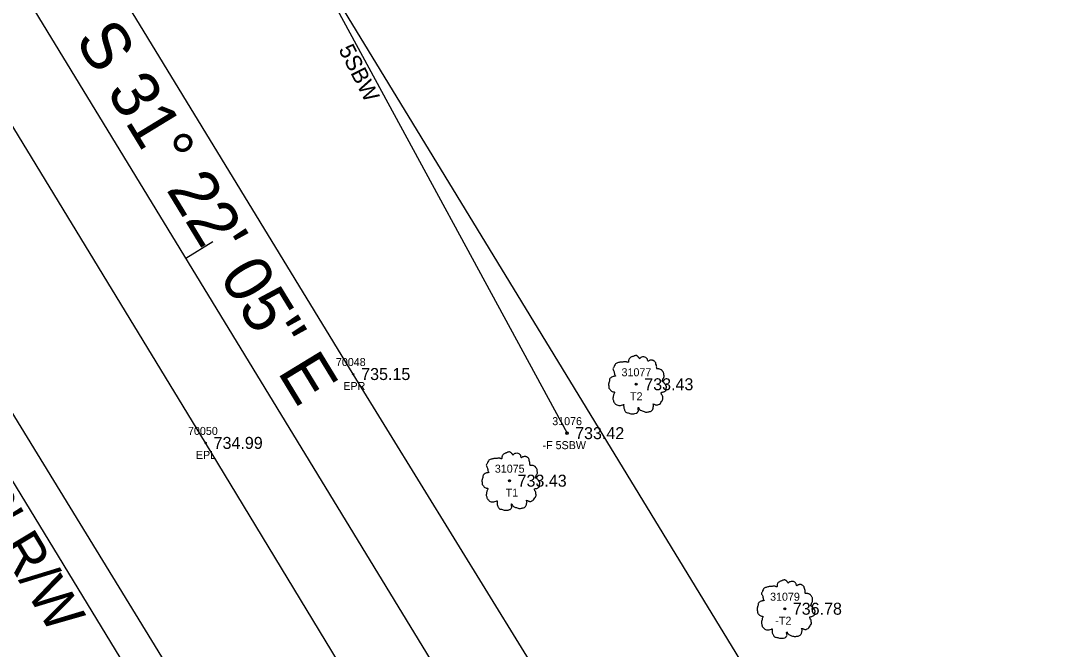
# Model space of a CAD drawing. Extents: x 1375131 to 1378678, y 999028 to 1004053.
# Drawn here: x 1377739.9 to 1377868.1, y 1000960.8 to 1001039.4 of the extents above; entities that cross this region are included whole.
import ezdxf

# ---------------------------------------------------------------- set-up
doc = ezdxf.new("R2010")
doc.units = 0
for name, color, linetype in [('RD_EX_Fence_Other', 7, 'Continuous'), ('RD_EX_Fence_Other_txCode', 7, 'Continuous'), ('RD_EX_Road', 7, 'Continuous'), ('RD_EX_Road_txCode', 7, 'Continuous'), ('RD_EX_RW', 7, 'Continuous'), ('RD_EX_RW_TX', 7, 'Continuous'), ('RD_EX_SU_Elec', 7, 'Continuous'), ('RD_EX_TX_Fence_Other_ELEV', 7, 'Continuous'), ('RD_EX_TX_Road_ELEV', 7, 'Continuous'), ('RD_EX_TX_VEG_ELEV', 7, 'Continuous'), ('RD_EX_VEG', 7, 'Continuous'), ('RD_EX_VEG_txCode', 7, 'Continuous'), ('RD_HC_Cl', 7, 'Continuous'), ('RD_HC_Data', 7, 'Continuous'), ('RD_HC_Data_Tic', 7, 'Continuous'), ('RD_SMD_Locator', 7, 'Continuous'), ('RD_TX_Misc2', 7, 'Continuous')]:
    doc.layers.add(name, color=color, linetype=linetype)

msp = doc.modelspace()

# ---------------------------------------------------------------- linework, layer by layer
at = {"layer": 'RD_EX_Fence_Other'}
msp.add_line((1377746.17, 1001102.37), (1377808.24, 1000987.87), dxfattribs=at)
at = {"layer": 'RD_EX_Road'}
for points in [[(1377899.67, 1000800.29), (1377898.72, 1000801.84), (1377870.31, 1000849.94), (1377847.28, 1000887.89), (1377815.15, 1000940.58), (1377781.51, 1000995.26), (1377748.62, 1001049.21), (1377716.58, 1001099.53), (1377686.67, 1001148.78), (1377656.47, 1001199.11), (1377629.54, 1001244.18), (1377599.89, 1001292.67), (1377570.87, 1001341.43), (1377539.83, 1001392.47), (1377511.01, 1001440.31), (1377480.72, 1001490), (1377449.73, 1001541.49), (1377420.9, 1001591.95), (1377390.45, 1001644.41)], [(1377883.75, 1000788.5), (1377882.63, 1000790.22), (1377852.26, 1000839.6), (1377828.46, 1000879.31), (1377797, 1000930.66), (1377763.07, 1000986.65), (1377731.87, 1001037.81), (1377700.31, 1001089.98), (1377670.43, 1001138.24), (1377639.73, 1001190.03), (1377611.89, 1001234.23), (1377582.78, 1001282.57), (1377552.22, 1001331.03), (1377522.24, 1001382.35), (1377494.26, 1001430.19), (1377463.17, 1001481.14), (1377433.42, 1001531.29), (1377403.14, 1001580.98), (1377371.36, 1001632.19)]]:
    msp.add_lwpolyline(points, dxfattribs=at)
at = {"layer": 'RD_EX_RW'}
for p, q in [((1377592.75, 1001348.44), (1377983.57, 1000707.36)), ((1377536.4, 1001314.08), (1377927.22, 1000673.01))]:
    msp.add_line(p, q, dxfattribs=at)
at = {"layer": 'RD_EX_SU_Elec'}
msp.add_lwpolyline([(1377525.76, 1001454.69), (1377578.78, 1001251.81), (1377798.03, 1000893.79)], dxfattribs=at)
at = {"layer": 'RD_EX_VEG'}
for centre, radius in [((1377816.88, 1000993.98), 0.125), ((1377816.87, 1000993.97), 0.00005), ((1377801.05, 1000981.93), 0.125), ((1377801.04, 1000981.92), 0.00005), ((1377835.44, 1000965.93), 0.125), ((1377835.43, 1000965.92), 0.00005)]:
    msp.add_circle(centre, radius, dxfattribs=at)
for points in [[(1377816.94, 1000997.56), (1377816.79, 1000997.57), (1377816.63, 1000997.52), (1377816.5, 1000997.47), (1377816.39, 1000997.44), (1377816.28, 1000997.39), (1377816.13, 1000997.3), (1377816.02, 1000997.2), (1377815.95, 1000997.07), (1377815.93, 1000996.96), (1377815.9, 1000996.82), (1377815.9, 1000996.74), (1377815.84, 1000996.72), (1377815.77, 1000996.74), (1377815.64, 1000996.77), (1377815.52, 1000996.77), (1377815.39, 1000996.77), (1377815.22, 1000996.76), (1377815.04, 1000996.76), (1377814.9, 1000996.74), (1377814.74, 1000996.71), (1377814.55, 1000996.65), (1377814.38, 1000996.59), (1377814.23, 1000996.46), (1377814.1, 1000996.22), (1377814.04, 1000996.05), (1377813.97, 1000995.92), (1377814.04, 1000995.7), (1377814.13, 1000995.53), (1377814.14, 1000995.43), (1377814.18, 1000995.21), (1377814.23, 1000995.1), (1377814.29, 1000995), (1377814.25, 1000994.99), (1377814.07, 1000994.96), (1377813.92, 1000994.91), (1377813.7, 1000994.8), (1377813.59, 1000994.69), (1377813.54, 1000994.53), (1377813.53, 1000994.35), (1377813.48, 1000994.25), (1377813.44, 1000994.11), (1377813.43, 1000994.08), (1377813.41, 1000993.91), (1377813.46, 1000993.69), (1377813.47, 1000993.51), (1377813.53, 1000993.4), (1377813.6, 1000993.31), (1377813.69, 1000993.19), (1377813.89, 1000993.08), (1377814.05, 1000993.03), (1377814.15, 1000993.01), (1377814.07, 1000992.76), (1377814.04, 1000992.59), (1377813.98, 1000992.39), (1377813.98, 1000992.35), (1377813.95, 1000992.11), (1377814.03, 1000991.95), (1377814.07, 1000991.76), (1377814.15, 1000991.65), (1377814.29, 1000991.5), (1377814.45, 1000991.39), (1377814.7, 1000991.33), (1377814.9, 1000991.34), (1377815.19, 1000991.43), (1377815.32, 1000991.46), (1377815.3, 1000991.38), (1377815.32, 1000991.19), (1377815.32, 1000990.98), (1377815.39, 1000990.81), (1377815.44, 1000990.68), (1377815.52, 1000990.55), (1377815.68, 1000990.44), (1377815.88, 1000990.4), (1377816.09, 1000990.33), (1377816.32, 1000990.29), (1377816.57, 1000990.28), (1377816.87, 1000990.35), (1377817, 1000990.41), (1377817.05, 1000990.5), (1377817.15, 1000990.69), (1377817.13, 1000990.8), (1377817.14, 1000991.1), (1377817.19, 1000991.01), (1377817.28, 1000990.84), (1377817.53, 1000990.69), (1377817.73, 1000990.6), (1377817.97, 1000990.53), (1377818.12, 1000990.49), (1377818.35, 1000990.53), (1377818.54, 1000990.56), (1377818.73, 1000990.63), (1377818.88, 1000990.76), (1377818.97, 1000990.9), (1377818.99, 1000991.04), (1377819.03, 1000991.23), (1377819.05, 1000991.31)], [(1377819.05, 1000991.31), (1377819.02, 1000991.4), (1377818.99, 1000991.53), (1377819.03, 1000991.51), (1377819.12, 1000991.49), (1377819.25, 1000991.43), (1377819.36, 1000991.39), (1377819.53, 1000991.4), (1377819.66, 1000991.45), (1377819.89, 1000991.59), (1377820.03, 1000991.83), (1377820.16, 1000992.03), (1377820.2, 1000992.19), (1377820.18, 1000992.3), (1377820.16, 1000992.55), (1377820.06, 1000992.68), (1377820.04, 1000992.74), (1377819.99, 1000992.94), (1377820.03, 1000992.96), (1377820.16, 1000992.99), (1377820.35, 1000993.05), (1377820.49, 1000993.11), (1377820.6, 1000993.2), (1377820.64, 1000993.31), (1377820.63, 1000993.51), (1377820.65, 1000993.71), (1377820.61, 1000993.79), (1377820.56, 1000993.86), (1377820.53, 1000993.96), (1377820.45, 1000994.04), (1377820.4, 1000994.11), (1377820.35, 1000994.16), (1377820.29, 1000994.24), (1377820.2, 1000994.3), (1377820.13, 1000994.33), (1377820.1, 1000994.4), (1377820.18, 1000994.5), (1377820.2, 1000994.55), (1377820.21, 1000994.66), (1377820.33, 1000994.84), (1377820.35, 1000995.04), (1377820.33, 1000995.25), (1377820.3, 1000995.39), (1377820.23, 1000995.53), (1377820.13, 1000995.65), (1377820.06, 1000995.74), (1377819.98, 1000995.8), (1377819.81, 1000995.86), (1377819.69, 1000995.89), (1377819.51, 1000995.89), (1377819.41, 1000995.91), (1377819.43, 1000995.94), (1377819.43, 1000996.01), (1377819.43, 1000996.15), (1377819.39, 1000996.37), (1377819.31, 1000996.62), (1377819.31, 1000996.64), (1377819.26, 1000996.76), (1377819.15, 1000996.86), (1377819.07, 1000996.91), (1377818.97, 1000996.97), (1377818.84, 1000996.99), (1377818.69, 1000996.99), (1377818.55, 1000996.96), (1377818.45, 1000996.91), (1377818.37, 1000996.85), (1377818.33, 1000996.92), (1377818.28, 1000997.07), (1377818.25, 1000997.15), (1377818.18, 1000997.24), (1377818.07, 1000997.34), (1377817.84, 1000997.4), (1377817.53, 1000997.36), (1377817.38, 1000997.26), (1377817.3, 1000997.17), (1377817.28, 1000997.24), (1377817.18, 1000997.34), (1377817.13, 1000997.42), (1377817.04, 1000997.49), (1377816.97, 1000997.54), (1377816.92, 1000997.56)], [(1377801.11, 1000985.51), (1377800.97, 1000985.53), (1377800.8, 1000985.48), (1377800.68, 1000985.43), (1377800.57, 1000985.39), (1377800.45, 1000985.34), (1377800.3, 1000985.25), (1377800.19, 1000985.15), (1377800.13, 1000985.03), (1377800.1, 1000984.91), (1377800.08, 1000984.78), (1377800.08, 1000984.69), (1377800.02, 1000984.68), (1377799.94, 1000984.69), (1377799.82, 1000984.73), (1377799.69, 1000984.73), (1377799.57, 1000984.73), (1377799.39, 1000984.71), (1377799.22, 1000984.71), (1377799.08, 1000984.69), (1377798.92, 1000984.67), (1377798.73, 1000984.6), (1377798.55, 1000984.54), (1377798.4, 1000984.42), (1377798.28, 1000984.18), (1377798.22, 1000984), (1377798.14, 1000983.88), (1377798.22, 1000983.65), (1377798.3, 1000983.48), (1377798.32, 1000983.38), (1377798.35, 1000983.17), (1377798.4, 1000983.05), (1377798.47, 1000982.95), (1377798.43, 1000982.94), (1377798.24, 1000982.92), (1377798.09, 1000982.87), (1377797.88, 1000982.75), (1377797.77, 1000982.64), (1377797.72, 1000982.48), (1377797.7, 1000982.3), (1377797.65, 1000982.2), (1377797.62, 1000982.07), (1377797.6, 1000982.03), (1377797.58, 1000981.87), (1377797.63, 1000981.64), (1377797.64, 1000981.47), (1377797.7, 1000981.35), (1377797.78, 1000981.27), (1377797.87, 1000981.14), (1377798.07, 1000981.03), (1377798.23, 1000980.98), (1377798.33, 1000980.97), (1377798.24, 1000980.72), (1377798.22, 1000980.54), (1377798.15, 1000980.34), (1377798.15, 1000980.3), (1377798.13, 1000980.07), (1377798.2, 1000979.9), (1377798.24, 1000979.72), (1377798.33, 1000979.6), (1377798.47, 1000979.45), (1377798.63, 1000979.34), (1377798.88, 1000979.28), (1377799.08, 1000979.29), (1377799.37, 1000979.38), (1377799.49, 1000979.42), (1377799.48, 1000979.33), (1377799.49, 1000979.14), (1377799.49, 1000978.93), (1377799.57, 1000978.77), (1377799.62, 1000978.63), (1377799.69, 1000978.51), (1377799.85, 1000978.39), (1377800.05, 1000978.36), (1377800.27, 1000978.28), (1377800.49, 1000978.24), (1377800.74, 1000978.23), (1377801.04, 1000978.31), (1377801.18, 1000978.37), (1377801.23, 1000978.46), (1377801.33, 1000978.64), (1377801.3, 1000978.76), (1377801.31, 1000979.05), (1377801.36, 1000978.97), (1377801.45, 1000978.79), (1377801.7, 1000978.64), (1377801.9, 1000978.56), (1377802.14, 1000978.48), (1377802.29, 1000978.44), (1377802.53, 1000978.48), (1377802.71, 1000978.52), (1377802.9, 1000978.58), (1377803.05, 1000978.72), (1377803.14, 1000978.86), (1377803.16, 1000978.99), (1377803.2, 1000979.18), (1377803.23, 1000979.27)], [(1377803.23, 1000979.27), (1377803.19, 1000979.35), (1377803.16, 1000979.48), (1377803.2, 1000979.47), (1377803.29, 1000979.44), (1377803.43, 1000979.38), (1377803.54, 1000979.34), (1377803.7, 1000979.35), (1377803.84, 1000979.4), (1377804.06, 1000979.54), (1377804.2, 1000979.78), (1377804.34, 1000979.98), (1377804.38, 1000980.14), (1377804.35, 1000980.25), (1377804.34, 1000980.5), (1377804.24, 1000980.63), (1377804.21, 1000980.69), (1377804.16, 1000980.89), (1377804.2, 1000980.92), (1377804.34, 1000980.94), (1377804.53, 1000981), (1377804.66, 1000981.07), (1377804.78, 1000981.15), (1377804.81, 1000981.27), (1377804.8, 1000981.47), (1377804.83, 1000981.67), (1377804.79, 1000981.74), (1377804.74, 1000981.82), (1377804.7, 1000981.92), (1377804.63, 1000981.99), (1377804.58, 1000982.07), (1377804.53, 1000982.12), (1377804.46, 1000982.19), (1377804.38, 1000982.25), (1377804.3, 1000982.28), (1377804.28, 1000982.35), (1377804.35, 1000982.45), (1377804.38, 1000982.5), (1377804.39, 1000982.62), (1377804.5, 1000982.79), (1377804.53, 1000982.99), (1377804.5, 1000983.2), (1377804.48, 1000983.34), (1377804.4, 1000983.48), (1377804.3, 1000983.6), (1377804.24, 1000983.69), (1377804.15, 1000983.75), (1377803.99, 1000983.82), (1377803.86, 1000983.84), (1377803.69, 1000983.84), (1377803.59, 1000983.87), (1377803.6, 1000983.89), (1377803.6, 1000983.97), (1377803.6, 1000984.1), (1377803.56, 1000984.33), (1377803.49, 1000984.58), (1377803.49, 1000984.59), (1377803.44, 1000984.71), (1377803.33, 1000984.81), (1377803.24, 1000984.86), (1377803.14, 1000984.93), (1377803.01, 1000984.94), (1377802.86, 1000984.94), (1377802.73, 1000984.91), (1377802.63, 1000984.86), (1377802.54, 1000984.8), (1377802.5, 1000984.88), (1377802.45, 1000985.03), (1377802.43, 1000985.1), (1377802.35, 1000985.19), (1377802.24, 1000985.29), (1377802.01, 1000985.35), (1377801.7, 1000985.31), (1377801.55, 1000985.21), (1377801.48, 1000985.13), (1377801.45, 1000985.19), (1377801.35, 1000985.29), (1377801.3, 1000985.38), (1377801.21, 1000985.44), (1377801.14, 1000985.49), (1377801.09, 1000985.51)], [(1377835.5, 1000969.51), (1377835.36, 1000969.53), (1377835.19, 1000969.48), (1377835.07, 1000969.43), (1377834.96, 1000969.39), (1377834.84, 1000969.34), (1377834.69, 1000969.25), (1377834.58, 1000969.15), (1377834.52, 1000969.03), (1377834.49, 1000968.91), (1377834.47, 1000968.78), (1377834.47, 1000968.69), (1377834.41, 1000968.68), (1377834.33, 1000968.69), (1377834.21, 1000968.73), (1377834.08, 1000968.73), (1377833.96, 1000968.73), (1377833.78, 1000968.71), (1377833.61, 1000968.71), (1377833.47, 1000968.69), (1377833.31, 1000968.66), (1377833.12, 1000968.6), (1377832.94, 1000968.54), (1377832.79, 1000968.41), (1377832.67, 1000968.18), (1377832.61, 1000968), (1377832.53, 1000967.88), (1377832.61, 1000967.65), (1377832.69, 1000967.48), (1377832.71, 1000967.38), (1377832.74, 1000967.16), (1377832.79, 1000967.05), (1377832.86, 1000966.95), (1377832.82, 1000966.94), (1377832.63, 1000966.91), (1377832.48, 1000966.86), (1377832.27, 1000966.75), (1377832.16, 1000966.64), (1377832.11, 1000966.48), (1377832.09, 1000966.3), (1377832.04, 1000966.2), (1377832.01, 1000966.07), (1377831.99, 1000966.03), (1377831.97, 1000965.87), (1377832.02, 1000965.64), (1377832.03, 1000965.47), (1377832.09, 1000965.35), (1377832.17, 1000965.27), (1377832.26, 1000965.14), (1377832.46, 1000965.03), (1377832.62, 1000964.98), (1377832.72, 1000964.97), (1377832.63, 1000964.72), (1377832.61, 1000964.54), (1377832.54, 1000964.34), (1377832.54, 1000964.3), (1377832.52, 1000964.07), (1377832.59, 1000963.9), (1377832.63, 1000963.72), (1377832.72, 1000963.6), (1377832.86, 1000963.45), (1377833.02, 1000963.34), (1377833.27, 1000963.28), (1377833.47, 1000963.29), (1377833.76, 1000963.38), (1377833.88, 1000963.42), (1377833.87, 1000963.33), (1377833.88, 1000963.14), (1377833.88, 1000962.93), (1377833.96, 1000962.77), (1377834.01, 1000962.63), (1377834.08, 1000962.5), (1377834.24, 1000962.39), (1377834.44, 1000962.35), (1377834.66, 1000962.28), (1377834.88, 1000962.24), (1377835.13, 1000962.23), (1377835.43, 1000962.3), (1377835.57, 1000962.37), (1377835.62, 1000962.45), (1377835.72, 1000962.64), (1377835.69, 1000962.75), (1377835.7, 1000963.05), (1377835.75, 1000962.97), (1377835.84, 1000962.79), (1377836.09, 1000962.64), (1377836.29, 1000962.55), (1377836.53, 1000962.48), (1377836.68, 1000962.44), (1377836.92, 1000962.48), (1377837.1, 1000962.52), (1377837.29, 1000962.58), (1377837.44, 1000962.72), (1377837.53, 1000962.85), (1377837.55, 1000962.99), (1377837.59, 1000963.18), (1377837.62, 1000963.27)], [(1377837.62, 1000963.27), (1377837.58, 1000963.35), (1377837.55, 1000963.48), (1377837.59, 1000963.47), (1377837.68, 1000963.44), (1377837.82, 1000963.38), (1377837.93, 1000963.34), (1377838.09, 1000963.35), (1377838.23, 1000963.4), (1377838.45, 1000963.54), (1377838.59, 1000963.78), (1377838.73, 1000963.98), (1377838.77, 1000964.14), (1377838.74, 1000964.25), (1377838.73, 1000964.5), (1377838.63, 1000964.63), (1377838.6, 1000964.69), (1377838.55, 1000964.89), (1377838.59, 1000964.92), (1377838.73, 1000964.94), (1377838.92, 1000965), (1377839.05, 1000965.07), (1377839.17, 1000965.15), (1377839.2, 1000965.27), (1377839.19, 1000965.47), (1377839.22, 1000965.67), (1377839.18, 1000965.74), (1377839.13, 1000965.82), (1377839.09, 1000965.92), (1377839.02, 1000965.99), (1377838.97, 1000966.07), (1377838.92, 1000966.12), (1377838.85, 1000966.19), (1377838.77, 1000966.25), (1377838.69, 1000966.28), (1377838.67, 1000966.35), (1377838.74, 1000966.45), (1377838.77, 1000966.5), (1377838.78, 1000966.61), (1377838.89, 1000966.79), (1377838.92, 1000966.99), (1377838.89, 1000967.2), (1377838.87, 1000967.34), (1377838.79, 1000967.48), (1377838.69, 1000967.6), (1377838.63, 1000967.69), (1377838.54, 1000967.75), (1377838.38, 1000967.81), (1377838.25, 1000967.84), (1377838.08, 1000967.84), (1377837.98, 1000967.86), (1377837.99, 1000967.89), (1377837.99, 1000967.96), (1377837.99, 1000968.1), (1377837.95, 1000968.33), (1377837.88, 1000968.58), (1377837.88, 1000968.59), (1377837.83, 1000968.71), (1377837.72, 1000968.81), (1377837.63, 1000968.86), (1377837.53, 1000968.93), (1377837.4, 1000968.94), (1377837.25, 1000968.94), (1377837.12, 1000968.91), (1377837.02, 1000968.86), (1377836.93, 1000968.8), (1377836.89, 1000968.88), (1377836.84, 1000969.03), (1377836.82, 1000969.1), (1377836.74, 1000969.19), (1377836.63, 1000969.29), (1377836.4, 1000969.35), (1377836.09, 1000969.31), (1377835.94, 1000969.21), (1377835.87, 1000969.13), (1377835.84, 1000969.19), (1377835.74, 1000969.29), (1377835.69, 1000969.38), (1377835.6, 1000969.44), (1377835.53, 1000969.49), (1377835.48, 1000969.51)]]:
    msp.add_spline(points, degree=3, dxfattribs=at)
at = {"layer": 'RD_HC_Cl'}
msp.add_line((1377564.57, 1001331.26), (1377955.4, 1000690.18), dxfattribs=at)
at = {"layer": 'RD_HC_Data_Tic'}
msp.add_line((1377760.58, 1001009.75), (1377763.99, 1001011.83), dxfattribs=at)
at = {"layer": 'RD_SMD_Locator'}
for centre, radius in [((1377781.51, 1000995.26), 0.075), ((1377816.88, 1000993.98), 0.075), ((1377808.24, 1000987.87), 0.15), ((1377763.07, 1000986.65), 0.075), ((1377801.05, 1000981.93), 0.075), ((1377835.44, 1000965.93), 0.075)]:
    msp.add_circle(centre, radius, dxfattribs=at)

# ---------------------------------------------------------------- texts
at = {"layer": 'RD_EX_Fence_Other_txCode'}
for s, p in [('31076', (1377806.38, 1000988.87)), ('-F 5SBW', (1377805.17, 1000985.87))]:
    msp.add_text(s, height=1, dxfattribs=at).set_placement(p)
at = {"layer": 'RD_EX_Road_txCode'}
for s, p in [('70048', (1377779.35, 1000996.26)), ('EPR', (1377780.28, 1000993.26)), ('70050', (1377760.87, 1000987.65)), ('EPL', (1377761.86, 1000984.65))]:
    msp.add_text(s, height=1, dxfattribs=at).set_placement(p)
at = {"layer": 'RD_EX_RW_TX'}
msp.add_text("PRESENT 33.0' R/W", height=5, rotation=301.1045, dxfattribs=at).set_placement((1377711.56, 1001016.12))
at = {"layer": 'RD_EX_TX_Fence_Other_ELEV'}
msp.add_text('733.42', height=1.5, dxfattribs=at).set_placement((1377809.24, 1000987.12))
at = {"layer": 'RD_EX_TX_Road_ELEV'}
for s, p in [('735.15', (1377782.51, 1000994.51)), ('734.99', (1377764.07, 1000985.9))]:
    msp.add_text(s, height=1.5, dxfattribs=at).set_placement(p)
at = {"layer": 'RD_EX_TX_VEG_ELEV'}
for s, p in [('733.43', (1377817.88, 1000993.23)), ('733.43', (1377802.05, 1000981.18)), ('736.78', (1377836.44, 1000965.18))]:
    msp.add_text(s, height=1.5, dxfattribs=at).set_placement(p)
at = {"layer": 'RD_EX_VEG_txCode'}
for s, p in [('31077', (1377815.04, 1000994.98)), ('T2', (1377816.1, 1000991.98)), ('31075', (1377799.21, 1000982.93)), ('T1', (1377800.56, 1000979.93)), ('31079', (1377833.6, 1000966.93)), ('-T2', (1377834.26, 1000963.93))]:
    msp.add_text(s, height=1, dxfattribs=at).set_placement(p)
at = {"layer": 'RD_HC_Data'}
msp.add_text('S 31%%d 22\' 05" E', height=6, rotation=301.368, dxfattribs=at).set_placement((1377746.66, 1001037.07))
at = {"layer": 'RD_TX_Misc2'}
msp.add_text('5SBW', height=2, rotation=297.0046, dxfattribs=at).set_placement((1377779.64, 1001035.83))

doc.saveas('drawing.dxf')
